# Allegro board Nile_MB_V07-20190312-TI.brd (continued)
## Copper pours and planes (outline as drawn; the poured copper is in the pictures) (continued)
N14284448 on BOTTOM (solid shape): 70.55,32.27 70.85,32.27 71.15,31.97 71.15,31.37 70.8,31.02 68.6,31.02 68.25,30.67 68.25,29.22 68.1,29.07 66.25,29.07 65.85,29.47 65.85,30.37 65.65,30.57 64.6,30.57 64.55,30.62 64.55,32.67 64.6,32.72 69.45,32.72 69.65,32.92 69.9,32.92
N14502607 on BOTTOM (solid shape): 33.76,49.29 33.75,39.27 33.3,38.87 32.35,38.87 31.55,38.92 31.5,39.77 31.51,39.87 31.78,40.15 32.08,40.49 32.4,40.93 32.74,42 32.77,43.79 32.68,45.37 32.39,46.07 30.75,47.71 30.48,47.71 30.44,47.75 30.44,49.8 33.25,49.8
N14502607 on INNER LAYER 9 (solid shape): 33.81,49.35 33.81,39.97 32.91,39.07 31.79,39.07 31.69,39.17 31.69,40.6 32.58,41.49 32.58,45.78 30.38,47.98 30.38,49.43 30.76,49.81 33.35,49.81
N15638560 on BOTTOM (solid shape): 68.5,33.82 68.25,33.57 65.15,33.57 65.1,33.62 65.1,34.52 66.65,34.52 67.1,34.97 68.5,34.97
N15725552 on BOTTOM (solid shape): 60.95,16.32 59.8,15.17 58.8,15.17 58.8,17.22 59.1,17.52 60.95,17.52
N15851698 on BOTTOM (solid shape): 68.25,28.22 68.25,27.27 66.1,25.12 65.2,25.12 64.65,25.67 64.65,27.67 65.25,28.27 68.2,28.27
N15883520 on BOTTOM (solid shape): 22.76,35.06 22.76,33.26 21.11,33.26 21.01,33.36 21.01,34.31 20.81,34.51 18.16,34.51 18.16,33.86 18.01,33.71 17.46,33.71 17.31,33.86 17.31,35.51 17.86,36.06 21.76,36.06
N15888229 on BOTTOM (solid shape): 23.21,36.41 22.06,36.41 22.06,37.31 23.21,37.31
N15888229 on BOTTOM (solid shape): 22.76,30.51 22.76,30.01 23.16,29.61 24.06,29.61 24.21,29.46 24.21,28.51 24.01,28.31 24.01,26.81 24.46,26.36 24.46,25.41 24.41,25.36 22.66,25.36 22.36,25.66 22.36,27.96 22.86,28.46 22.86,29.06 22.46,29.46 21.71,29.46 21.51,29.66 21.51,30.56 22.71,30.56
N15888229 on INNER LAYER 8 (solid shape): 23.16,37.06 23.16,36.36 23.11,36.31 22.01,36.31 21.91,36.41 21.91,37.16 21.96,37.21 23.01,37.21
N15888229 on INNER LAYER 8 (solid shape): 24.16,29.26 24.16,28.71 23.91,28.46 23.06,28.46 22.71,28.81 22.71,29.56 22.96,29.81 23.61,29.81
N15888229 on INNER LAYER 9 (solid shape): 22.81,30.31 22.81,29.96 22.96,29.81 24.06,29.81 24.26,29.61 24.26,28.51 24.11,28.36 22.36,28.36 21.46,29.26 21.46,30.31 21.56,30.41 22.71,30.41

Small or netless copper shapes (teardrops, artwork), in the pictures only: 12 on TOP, 23 on BOTTOM, 1 on INNER LAYER 2, 8 on INNER LAYER 3, 4 on INNER LAYER 4, 4 on INNER LAYER 5, 3 on INNER LAYER 6, 4 on INNER LAYER 7, 14 on INNER LAYER 8, 26 on INNER LAYER 9

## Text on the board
Ref Des/Silkscreen Bottom: BOT
User.Comments: 5.4000
Ref Des/Silkscreen Top: D- | GND | D+ | A | B | MAIN | NILE MAIN BOARD | Ver.07 | SUB | WIFI | GPS | TOP
DEVICE_TYPE_TOP: FIGURE | SIZE | 0.254 | 0.85 | 1.016 | 1.9 | 2.0 | 2.4 | 0.6 | 0.8 | 0.8001 | 1.1501 | 1.5 | 1.55 | 0.8499x0.65 | 1.25x0.7 | 1.4x0.6599 | 1.5001x0.8001 | 1.9x0.6 | 2.0x0.7 | 0.85x0.5 | 1.8001x0.8001 | DRILL CHART: TOP to BOTTOM | ALL UNITS ARE IN MILLIMETERS | TOLERANCE | +0.0/-0.0 | +0.075/-0.075 | +0.0762/-0.0762 | PLATED | NON-PLATED | QTY | 375 | 5 | 2 | 1 | 10 | 4
User.5: FIGURE | SIZE | 0.0762 | 0.1001 | DRILL CHART: TOP to INNER LAYER 3 | ALL UNITS ARE IN MILLIMETERS | TOLERANCE | +0.0/-0.0 | PLATED | QTY | 434 | 1304
User.6: FIGURE | SIZE | 0.0762 | 0.1001 | DRILL CHART: INNER LAYER 9 to BOTTOM | ALL UNITS ARE IN MILLIMETERS | TOLERANCE | +0.0/-0.0 | PLATED | QTY | 368 | 2096
User.7: FIGURE | SIZE | 0.0762 | 0.1001 | DRILL CHART: INNER LAYER 8 to INNER LAYER 9 | ALL UNITS ARE IN MILLIMETERS | TOLERANCE | +0.0/-0.0 | PLATED | QTY | 87 | 1604
User.8: FIGURE | SIZE | 0.2 | 0.2032 | DRILL CHART: INNER LAYER 3 to INNER LAYER 8 | ALL UNITS ARE IN MILLIMETERS | TOLERANCE | +0.0/-0.0 | PLATED | QTY | 364 | 1207
User.9: FIGURE | SIZE | 0.0762 | 0.1001 | DRILL CHART: INNER LAYER 8 to BOTTOM | ALL UNITS ARE IN MILLIMETERS | TOLERANCE | +0.0/-0.0 | PLATED | QTY | 844 | 531
User.10: FIGURE | SIZE | 0.0762 | 0.1001 | DRILL CHART: TOP to INNER LAYER 2 | ALL UNITS ARE IN MILLIMETERS | TOLERANCE | +0.0/-0.0 | PLATED | QTY | 183 | 1422
User.11: FIGURE | SIZE | 0.0762 | 0.1001 | DRILL CHART: INNER LAYER 2 to INNER LAYER 3 | ALL UNITS ARE IN MILLIMETERS | TOLERANCE | +0.0/-0.0 | PLATED | QTY | 106 | 854
